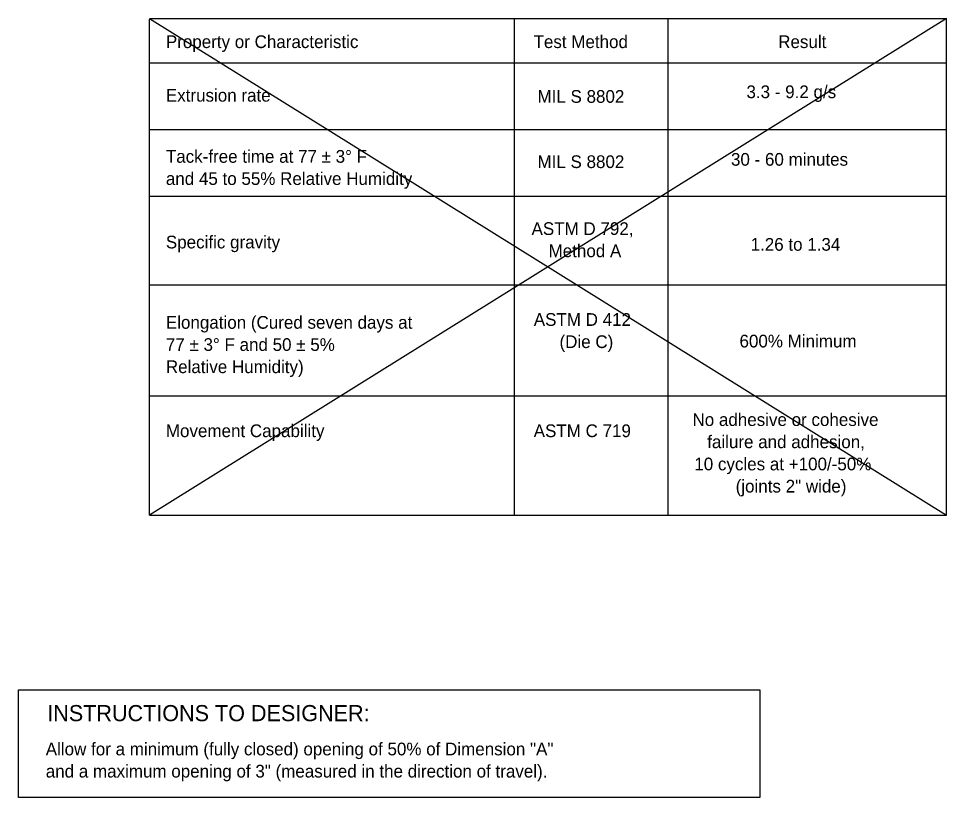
# Model space of a CAD drawing. Extents: x -7.9 to 27, y -3.1 to 14.6.
# Drawn here: x -7.87 to -2.35, y 4.33 to 8.96 of the extents above; entities that cross this region are included whole.
import ezdxf

# ---------------------------------------------------------------- set-up
doc = ezdxf.new("R2010")
doc.units = 0
for name, color, linetype in [('Border', 7, 'Continuous'), ('PlotBorder_dp', 7, 'Continuous'), ('TextMisc', 7, 'Continuous')]:
    doc.layers.add(name, color=color, linetype=linetype)

msp = doc.modelspace()

# ---------------------------------------------------------------- linework, layer by layer
at = {"layer": 'PlotBorder_dp'}
for p, q in [((-7.0884, 8.9618), (-2.3454, 8.9618)), ((-7.0884, 6.0067), (-7.0884, 8.9559)), ((-4.9159, 6.0067), (-4.9159, 8.9559)), ((-4.001, 6.0067), (-4.001, 8.9559)), ((-2.3454, 6.0067), (-2.3454, 8.9618)), ((-7.0884, 8.6977), (-2.3454, 8.6977)), ((-7.0884, 8.3016), (-2.3454, 8.3016)), ((-7.0884, 7.9056), (-2.3454, 7.9056)), ((-7.0884, 7.3774), (-2.3454, 7.3774)), ((-7.0884, 6.7173), (-2.3454, 6.7173)), ((-7.0884, 6.0067), (-2.3454, 6.0067))]:
    msp.add_line(p, q, dxfattribs=at)
at = {"layer": 'TextMisc'}
for p, q in [((-7.0884, 8.9618), (-2.3454, 6.0067)), ((-2.3454, 8.9618), (-7.0884, 6.0067))]:
    msp.add_line(p, q, dxfattribs=at)
msp.add_lwpolyline([(-7.8681, 4.9682), (-3.4568, 4.9682), (-3.4568, 4.3275), (-7.8681, 4.3275)], close=True, dxfattribs=at)

# ---------------------------------------------------------------- texts
at = {"layer": 'Border'}
for s, height, p in [('Property or Characteristic', 0.0756, (-6.9913, 8.7863)), ('Test Method', 0.0756, (-4.803, 8.7863)), ('Result', 0.0756, (-3.3467, 8.7863)), ('3.3 - 9.2 g/s', 0.0756, (-3.5356, 8.4883)), ('Extrusion rate', 0.0756, (-6.9913, 8.4675)), ('MIL S 8802', 0.0756, (-4.7795, 8.4606)), ('MIL S 8802', 0.0756, (-4.7795, 8.0724)), ('30 - 60 minutes', 0.0756, (-3.6278, 8.0863)), ('Specific gravity', 0.0756, (-6.9913, 7.5942)), ('1.26 to 1.34', 0.0756, (-3.511, 7.5804)), ('600% Minimum', 0.0756, (-3.5771, 7.005)), ('Movement Capability', 0.0756, (-6.9913, 6.4713)), ('ASTM C 719', 0.0756, (-4.802, 6.4713)), ('INSTRUCTIONS TO DESIGNER:', 0.096, (-7.6973, 4.7812))]:
    msp.add_text(s, height=height, dxfattribs=at).set_placement(p)
at = {"layer": 'PlotBorder_dp'}
for s, p in [('Tack-free time at 77 ± 3° F', (-6.9913, 8.1038)), ('and 45 to 55% Relative Humidity', (-6.9913, 7.9718)), ('ASTM D 792,', (-4.8149, 7.6741)), ('Method A', (-4.7133, 7.5421)), ('Elongation (Cured seven days at', (-6.9913, 7.1163)), ('ASTM D 412', (-4.8015, 7.1334)), ('(Die C)', (-4.6484, 7.0014)), ('77 ± 3° F and 50 ± 5%', (-6.9913, 6.9843)), ('Relative Humidity) ', (-6.9913, 6.8523)), ('No adhesive or cohesive ', (-3.8569, 6.5377)), ('failure and adhesion, ', (-3.7693, 6.4057)), ('10 cycles at +100/-50% ', (-3.846, 6.2737)), ('(joints 2" wide)', (-3.6001, 6.1417)), ('Allow for a minimum (fully closed) opening of 50% of Dimension "A" ', (-7.7063, 4.5779)), ('and a maximum opening of 3" (measured in the direction of travel).', (-7.7063, 4.4459))]:
    msp.add_text(s, height=0.0756, dxfattribs=at).set_placement(p)

doc.saveas('drawing.dxf')
